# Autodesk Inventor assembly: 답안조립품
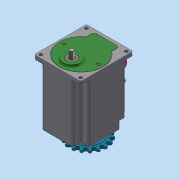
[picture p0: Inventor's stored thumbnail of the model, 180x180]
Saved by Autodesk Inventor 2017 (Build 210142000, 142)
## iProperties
Part Number: 답안조립품
Material: 일반
Document SubType Name: Assembly
Designer: MRC
Author: MRC
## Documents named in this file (16)
- C:\Users\MRC\Desktop\720212V1001\720212V1001\답안조립품.iam
- C:\Users\MRC\Desktop\720212V1001\720212V1001\본체.ipt
- C:\Users\MRC\Desktop\720212V1001\720212V1001\멈춤나사 M3.ipt
- C:\Users\MRC\Desktop\720212V1001\720212V1001\메인 축.ipt
- C:\Users\MRC\Desktop\720212V1001\720212V1001\베어링 608.ipt
- C:\Users\MRC\Desktop\720212V1001\720212V1001\베어링 6003.ipt
- C:\Users\MRC\Desktop\720212V1001\720212V1001\볼트 M4 x 10.ipt
- C:\Users\MRC\Desktop\720212V1001\720212V1001\부시.ipt
- C:\Users\MRC\Desktop\720212V1001\720212V1001\상부 캡.ipt
- C:\Users\MRC\Desktop\720212V1001\720212V1001\서브 축.ipt
- C:\Users\MRC\Desktop\720212V1001\720212V1001\스프로킷.ipt
- C:\Users\MRC\Desktop\720212V1001\720212V1001\슬라이더.ipt
- C:\Users\MRC\Desktop\720212V1001\720212V1001\오일 실 8 x 22 x 7.ipt
- C:\Users\MRC\Desktop\720212V1001\720212V1001\오일 실 17 x 32 x 8.ipt
- C:\Users\MRC\Desktop\720212V1001\720212V1001\커버.ipt
- C:\Users\MRC\Desktop\720212V1001\720212V1001\키 5 x 5.ipt
